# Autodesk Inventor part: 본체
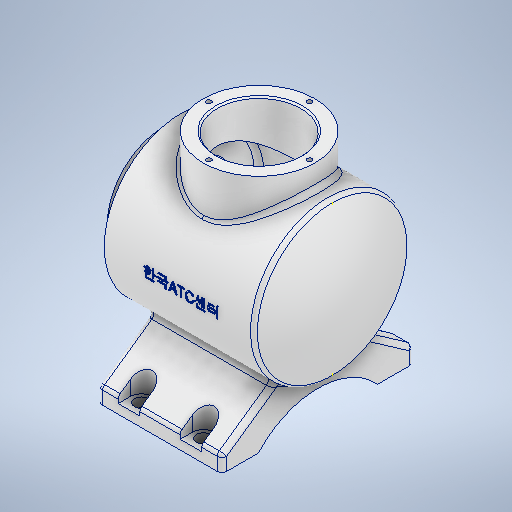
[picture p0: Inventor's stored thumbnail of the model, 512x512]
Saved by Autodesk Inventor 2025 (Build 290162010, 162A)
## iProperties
Created: 2024-07
Part Number: 본체
Material: 알루미늄 6061
Document SubType Name: Modeling
Designer: Admin
Density: 2.7 g/cm^3
Appearance: 알루미늄 - 평지
Mass: 1332.66 g
Surface Area: 1062.33 cm^2
Volume: 493.576 cm^3
Author: Admin
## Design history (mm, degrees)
sketch "스케치1"
  geometry: L1 (-47, 0)-(65, 0); L2 (0, 50)-(96.336, 50); L3 (96.336, 50)-(96.336, 0); L4 (96.336, 0)-(0, 0); L5 (0, 0)-(0, 50); L6 (108, 0)-(0, 0); L7 (108, 0)-(0, 0); A1 r 113 centre (-5, 0) between (108, 0) and (96.336, 50); 5 further points
  constraints: 14 end point, 2 horizontal, 2 parallel, 2 point on circle, 1 centre point, 1 coincident, 1 collinear, 1 perpendicular
  dimensions: "d7" = 108 distance of L6.start point (0, 0); "d9" = 50 distance of L4.end L2.start; "d108" = 113 radius of A1
revolve "회전1" sketch "스케치1" stored, may be unused: angle "d10" = 90 deg
fillet "모깎기1" dims "d11" = 3
sketch "스케치2"
  geometry: L1 (0, 0)-(0, -77); C1 r 36 at (0, 0)
  constraints: 2 end point, 1 centre point, 1 coincident, 1 vertical
  dimensions: "d12" = 77 distance of L1.start L1.end; "d13" = 72 diameter of C1
node "작업 평면3"
feature "쉘4" dims "d53" = 7
extrude "돌출2" join sketch "스케치2" distance "d29" = 12; taper "d30" = 0 deg
sketch "스케치5"
  geometry: L1 (97.166, 48.282)-(97.166, -48.282) reference; 1 further point
  node "투영된 루프1"
node "작업 평면4"
sketch "스케치6"
  geometry: L1 (12, -36)-(12, 36) reference; L2 (12, 0)-(-50, 0); C1 r 36 at (-50, 0); 1 further point
  constraints: 2 end point, 1 centre point, 1 coincident, 1 horizontal, 1 midpoint
  dimensions: "d32" = 62 distance of L2.start L2.end; "d33" = 72 diameter of C1
extrude "돌출3" join sketch "스케치6" stored distance "d34" = 12; taper "d35" = 0 deg
sketch "스케치7"
  geometry: C1 r 36 at (0, 0) reference; C2 r 27 at (0, 0); 1 further point
  constraints: 1 centre point, 1 coincident
  dimensions: "d36" = 54 diameter of C2
extrude "돌출4" cut sketch "스케치7" distance "d37" = 50; taper "d38" = 0 deg
sketch "스케치8"
  geometry: C1 r 27 at (0, 0); 1 further point
  constraints: 1 centre point, 1 coincident
  dimensions: "d39" = 54 diameter of C1
sketch "스케치4"
  geometry: L1 (-42.278, -26.694)-(-67, -62); L2 (-67, -62)-(-77, -62); L3 (-77, -62)-(-77, 62); L4 (-77, 62)-(-67, 62); L5 (-67, 62)-(-42.278, 26.694); L6 (0, 0)-(-77, 0); L7 (-77, 9.118)-(-77, 34.784); L8 (-77, -38.5)-(-77, 38.5); L9 (-77, -62)-(-77, 62); A1 r 50 centre (0, 0) between (-42.278, -26.694) and (-42.278, 26.694); A2 r 52.096 centre (-112.096, 0) between (-77, -38.5) and (-77, 38.5); 8 further points
  constraints: 18 end point, 5 midpoint, 5 point on circle, 3 coincident, 2 centre point, 2 perpendicular, 2 point on line, 1 collinear, 1 horizontal, 1 vertical, 2 other
  dimensions: "d22" = 55 deg angle of L4 L5; "d24" = 77 distance of L8.start L8.end; "d25" = 17 distance from line of L3 point (-60, 0); "d26" = 100 diameter of A1; "d82" = 77 distance from line of L9 point (0, 0); "d98" = 124 distance of point (-72, -62) point (-72, 62); "d107" = 10 distance of L3.end L4.end
extrude "돌출1" join sketch "스케치4" distance "d27" = 80; taper "d28" = 0 deg
extrude "돌출5" cut sketch "스케치8" distance "d45" = 50; taper "d46" = 0 deg
chamfer "모따기1" distance "d54" = 1; stored, may be unused: second distance "d55" = 2, angle "d56" = 45 deg
fillet "모깎기2" dims "d57" = 3
sketch "스케치10" dims "d58" = 65
  geometry: L1 (0, 0)-(0, 32.5); 1 further point
  constraints: 2 end point, 1 coincident, 1 vertical, 1 vertical alignment, 2 other
sketch "스케치11" dims "d59" = 65
  geometry: L1 (0, 0)-(32.5, 0); C1 r 36 at (0, 0) reference; 1 further point
  constraints: 2 end point, 1 coincident, 1 horizontal alignment, 2 other
hole "구멍1" sketch "스케치11" at (32.5, 0) diameter "d60" = 3.242; stored, may be unused: countersink angle "d64" = 90 deg, drill point angle "d66" = 120 deg; dims "d61" = 8, "d62" = 4, "d63" = 2, "d65" = 10
hole "구멍2" sketch "스케치10" diameter "d67" = 3.242; stored, may be unused: countersink angle "d71" = 90 deg, drill point angle "d73" = 120 deg; dims "d68" = 8, "d69" = 4, "d70" = 2, "d72" = 10
fillet "모깎기3" dims "d80" = 3
sketch "스케치12"
  geometry: 1 further point
sketch "스케치13"
  geometry: 1 further point
node "작업 평면6"
sketch "스케치14"
  geometry: L1 (-8, 62)-(-8, 38.5) reference; L2 (-8, 62)-(-8, 38.5) reference; L3 (-8, 38.5)-(-88, 38.5) reference; L4 (-88, 62)-(-88, 38.5) reference; L5 (-8, 62)-(-88, 62) reference; L6 (-8, 62)-(-28, 62); L7 (-28, 62)-(-68, 62); L8 (-21, 54)-(-35, 54); L9 (-35, 54)-(-35, 62); L10 (-35, 62)-(-21, 62); L11 (-21, 62)-(-21, 54); L12 (-75, 54)-(-61, 54); L13 (-61, 54)-(-61, 62); L14 (-61, 62)-(-75, 62); L15 (-75, 62)-(-75, 54); A1 r 7 centre (-28, 54) between (-35, 54) and (-21, 54); A2 r 7 centre (-68, 54) between (-75, 54) and (-61, 54); 5 further points
  constraints: 20 end point, 5 parallel, 4 midpoint, 4 point on circle, 2 centre point, 2 horizontal, 2 perpendicular, 2 point on line
  dimensions: "d84" = 20 distance of L6.end L2.start; "d85" = 40 distance of L6.end L7.end; "d86" = 14 distance of L8.start L8.end; "d87" = 14 distance of L12.start L12.end; "d88" = 8 distance of L8.end L9.end
  node "투영된 루프2"
extrude "돌출6" cut sketch "스케치14" distance "d89" = 20; taper "d90" = 0 deg
hole "구멍3" sketch "스케치14" diameter "d91" = 9; stored, may be unused: countersink angle "d95" = 90 deg, drill point angle "d97" = 0 deg; dims "d92" = 6, "d93" = 4, "d94" = 2, "d96" = 8
fillet "모깎기4" dims "d99" = 3
fillet "모깎기5" dims "d100" = 3
fillet "모깎기6" dims "d101" = 3
node "작업 평면8"
sketch "스케치16"
  geometry: L1 (0, 0)-(100, 0); L2 (-12, 36)-(-12, -36) reference; 2 further points
  constraints: 2 end point, 1 coincident, 1 horizontal, 1 midpoint, 1 other
  dimensions: "d103" = 62 distance from line of point (50, 0) L2
feature "엠보싱1" sketch "스케치16" dims "d7" = 108, "d9" = 50, "d104" = 0.5, "d105" = 0, "d108" = 113
feature "Υ耀Χ耀Ω耀Ϋ耀έ耀ί耀α耀γ耀" dims "d7" = 108, "d9" = 50, "d10" = 90 deg, "d11" = 3, "d12" = 77, "d13" = 72, "d21" = 8, "d22" = 55 deg, "d24" = 77, "d25" = 17, "d26" = 100, "d27" = 80, "d28" = 0, "d29" = 12, "d30" = 0, "d31" = 65, "d32" = 62, "d33" = 72, "d34" = 12, "d35" = 0, "d36" = 54, "d37" = 50, "d38" = 0, "d39" = 54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
node "솔리드1"
pattern_circular "원형 패턴1" dims angle "d75" = 360 deg
pattern_circular "원형 패턴2" dims angle "d78" = 360 deg
mirror "미러1"
feature "A9D066F2-1C7D-4E18-AEED-F7BC21143FA4" dims "d91" = 9, "d92" = 6, "d93" = 4, "d94" = 2, "d95" = 90 deg, "d96" = 8, "d97" = 0
